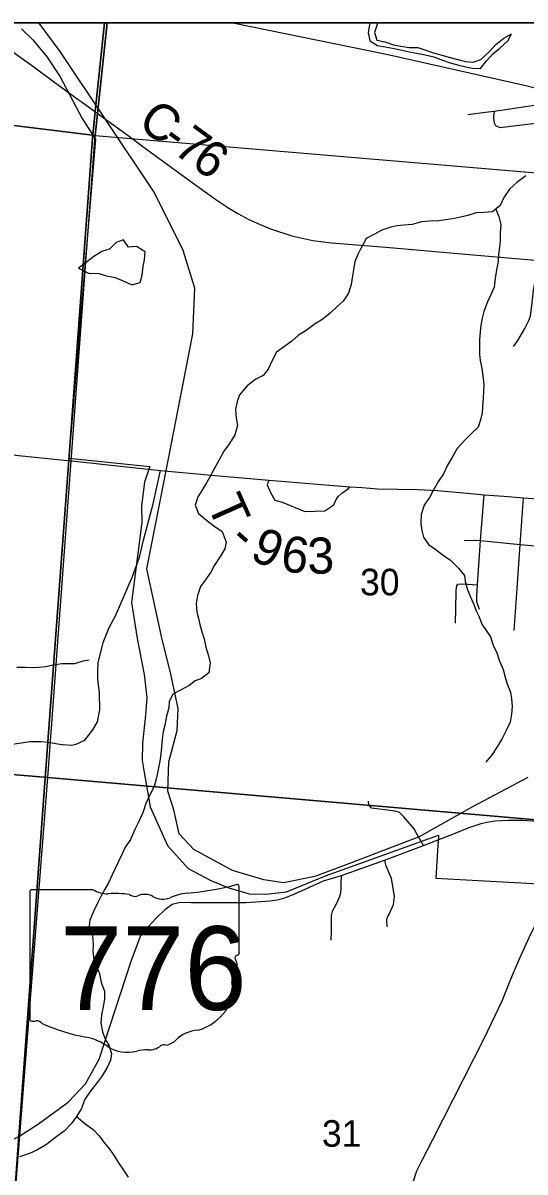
# Model space of a CAD drawing. Extents: x 0 to 42, y 0 to 22.
# Drawn here: x 2.271 to 2.666, y 19.995 to 20.9 of the extents above; entities that cross this region are included whole.
import ezdxf

# ---------------------------------------------------------------- set-up
doc = ezdxf.new("R2010")
doc.units = 0
for name, color, linetype in [('GM_X_City_Street', 7, 'Continuous'), ('GM_X_County_Road', 7, 'Continuous'), ('GM_X_County_Road_Text', 7, 'Continuous'), ('GM_X_Minor_Lake', 7, 'Continuous'), ('GM_X_Minor_River', 7, 'Continuous'), ('GM_X_Rail_Line', 7, 'Continuous'), ('GM_X_Section', 7, 'Continuous'), ('GM_X_Section_Text', 7, 'Continuous'), ('GM_X_State_Location', 7, 'Continuous'), ('GM_X_State_Route', 7, 'Continuous'), ('GM_X_State_Shield', 7, 'Continuous'), ('GM_X_Township_Road', 7, 'Continuous'), ('GM_X_Township_Road_Text', 7, 'Continuous'), ('GM_X_Unincorporated', 7, 'Continuous'), ('SH_Cut_Line', 7, 'Continuous'), ('SH_Data', 7, 'Continuous')]:
    doc.layers.add(name, color=color, linetype=linetype)

msp = doc.modelspace()

# ---------------------------------------------------------------- linework, layer by layer
at = {"layer": 'GM_X_City_Street'}
for points in [[(2.69353, 20.84243), (2.69352, 20.83798), (2.68544, 20.8369), (2.6506, 20.83163), (2.64714, 20.83111), (2.64496, 20.83077), (2.64156, 20.83021), (2.64126, 20.82626), (2.64118, 20.82527), (2.6417, 20.82134), (2.64286, 20.81923), (2.64611, 20.81767), (2.69164, 20.82305), (2.69375, 20.82356), (2.69547, 20.82473), (2.69654, 20.82659), (2.69573, 20.83522), (2.69441, 20.83772), (2.70111, 20.83974)], [(2.65681, 20.64514), (2.66032, 20.64991), (2.66593, 20.65926), (2.66875, 20.66505), (2.67022, 20.66916), (2.67142, 20.67721), (2.67273, 20.68948), (2.67716, 20.71289)], [(2.63006, 20.43787), (2.62809, 20.44409), (2.62809, 20.44853), (2.62858, 20.45731), (2.63105, 20.49224), (2.63388, 20.52836)], [(2.65749, 20.42134), (2.65981, 20.4545), (2.66213, 20.48923), (2.66487, 20.52594)], [(2.61812, 20.49239), (2.62596, 20.49264), (2.63105, 20.49224), (2.66213, 20.48923), (2.69114, 20.48647), (2.717, 20.4843), (2.74527, 20.48168), (2.79589, 20.47848), (2.83147, 20.47611), (2.86545, 20.47423)], [(2.61299, 20.4579), (2.61664, 20.4581), (2.62858, 20.45731)]]:
    msp.add_lwpolyline(points, dxfattribs=at)
at = {"layer": 'GM_X_County_Road'}
for points in [[(2.20921, 20.9), (2.22543, 20.89514), (2.24125, 20.88957), (2.25074, 20.88463), (2.26084, 20.87868), (2.27914, 20.86534)], [(2.27914, 20.86534), (2.2947, 20.85399), (2.31418, 20.83976)], [(2.31418, 20.83976), (2.31651, 20.83806), (2.32607, 20.83118)], [(2.32607, 20.83118), (2.32767, 20.83004), (2.33072, 20.82784), (2.33385, 20.82556)], [(2.33385, 20.82556), (2.35337, 20.81127), (2.36502, 20.80273), (2.38441, 20.78861), (2.4075, 20.77182), (2.42262, 20.76089), (2.43199, 20.75452), (2.43974, 20.74989), (2.44843, 20.74522), (2.45267, 20.74327)], [(2.45267, 20.74327), (2.45733, 20.74113), (2.46555, 20.73782), (2.48227, 20.73239), (2.4989, 20.72874), (2.51365, 20.72692), (2.55638, 20.72336), (2.62526, 20.71749), (2.67716, 20.71289), (2.68633, 20.71141), (2.69502, 20.70929), (2.70165, 20.7068), (2.70923, 20.70317), (2.7129, 20.70096)], [(2.30136, 20.33173), (2.30186, 20.33165), (2.30888, 20.33112), (2.31256, 20.33182), (2.31922, 20.33516), (2.32554, 20.34305), (2.32923, 20.34937), (2.33115, 20.35884), (2.33098, 20.37253), (2.32957, 20.38288), (2.32955, 20.38905), (2.32982, 20.39588), (2.33383, 20.41193), (2.33864, 20.42371), (2.34346, 20.43307), (2.357, 20.46397), (2.36231, 20.47917), (2.36526, 20.49142), (2.37308, 20.52124), (2.37897, 20.5476), (2.41898, 20.54388), (2.46428, 20.53976), (2.52797, 20.53458), (2.53771, 20.53402), (2.54991, 20.53312), (2.58119, 20.53245), (2.59708, 20.53164), (2.61455, 20.53024), (2.6205, 20.52966)], [(2.6205, 20.52966), (2.63388, 20.52836), (2.64928, 20.52713), (2.66487, 20.52594), (2.69112, 20.52409), (2.72008, 20.52113), (2.7486, 20.51783)], [(2.1, 20.25142), (2.10013, 20.25149), (2.12052, 20.26503), (2.17239, 20.30097), (2.18227, 20.30636), (2.19777, 20.31512), (2.20181, 20.31715), (2.20563, 20.31872), (2.2227, 20.32344), (2.23713, 20.32709), (2.26415, 20.33218), (2.27607, 20.33393), (2.28485, 20.3341), (2.29039, 20.33348), (2.30136, 20.33173)], [(2.59331, 20.02036), (2.63377, 20.09998), (2.64803, 20.12982), (2.65529, 20.14818), (2.66163, 20.1627), (2.67087, 20.18304), (2.67774, 20.19584), (2.68936, 20.21697), (2.69147, 20.22086)], [(2.49833, 19.78497), (2.50062, 19.79005), (2.50971, 19.80748), (2.53135, 19.84827), (2.54322, 19.8796), (2.58053, 19.99503), (2.5808, 19.99588), (2.58508, 20.00417), (2.59331, 20.02036)]]:
    msp.add_lwpolyline(points, dxfattribs=at)
at = {"layer": 'GM_X_Minor_Lake'}
for points in [[(2.36289, 20.69554), (2.36441, 20.70142), (2.36518, 20.70843), (2.36632, 20.71354), (2.3669, 20.7198), (2.36009, 20.72398), (2.35366, 20.72341), (2.34969, 20.72911), (2.34402, 20.72703), (2.33871, 20.72192), (2.33674, 20.72128)], [(2.33674, 20.72128), (2.33285, 20.72003), (2.32641, 20.71605), (2.32054, 20.71151), (2.31448, 20.70678), (2.32223, 20.70298), (2.33036, 20.70259), (2.33641, 20.70088), (2.34322, 20.69954), (2.35003, 20.6965), (2.35646, 20.69365), (2.36289, 20.69554)]]:
    msp.add_lwpolyline(points, dxfattribs=at)
at = {"layer": 'GM_X_Minor_River'}
for points in [[(2.54388, 20.9), (2.54325, 20.89719), (2.54248, 20.89226), (2.5438, 20.88581), (2.54985, 20.88239), (2.5559, 20.88125), (2.56157, 20.88011), (2.568, 20.87877), (2.575, 20.87725), (2.58086, 20.87629), (2.58748, 20.87496), (2.5941, 20.87324), (2.60091, 20.87058), (2.60715, 20.86868), (2.61377, 20.86678), (2.61944, 20.86544), (2.62455, 20.8643), (2.63098, 20.8641), (2.63553, 20.87016), (2.64102, 20.87584), (2.64594, 20.88001), (2.65238, 20.88587), (2.65542, 20.89156)], [(2.54982, 20.9), (2.54968, 20.89869), (2.5474, 20.89263), (2.54929, 20.88637), (2.55572, 20.88504), (2.56233, 20.88276), (2.5682, 20.8818), (2.57482, 20.88066), (2.58163, 20.88065), (2.58787, 20.87856), (2.59354, 20.87647), (2.59959, 20.87494), (2.60602, 20.87304), (2.61302, 20.87133), (2.61907, 20.86961), (2.62512, 20.86904), (2.63118, 20.8713), (2.6378, 20.87717), (2.6433, 20.88342), (2.64917, 20.88796), (2.65542, 20.89156)], [(2.66657, 20.77961), (2.65954, 20.77435), (2.65382, 20.76908), (2.64924, 20.76248), (2.64636, 20.75624), (2.64046, 20.75116), (2.63364, 20.75064), (2.62759, 20.75049), (2.62095, 20.74845), (2.61527, 20.74716), (2.61053, 20.74586), (2.60352, 20.74496), (2.59784, 20.74424), (2.59065, 20.74391), (2.5844, 20.74338), (2.57701, 20.74116), (2.57076, 20.74063), (2.56508, 20.7401), (2.56035, 20.73918), (2.55333, 20.73676), (2.54687, 20.73339), (2.5408, 20.73021), (2.53677, 20.72247), (2.53428, 20.71755), (2.53197, 20.71207), (2.53079, 20.70544), (2.53, 20.70071), (2.52901, 20.69408), (2.52707, 20.68727), (2.52286, 20.68085), (2.51811, 20.67671), (2.51258, 20.67144), (2.50669, 20.66674), (2.50061, 20.66299), (2.49281, 20.65716), (2.48768, 20.65416), (2.48235, 20.64946), (2.4776, 20.64589), (2.47018, 20.64063), (2.46692, 20.63421), (2.46366, 20.6274), (2.45965, 20.62231), (2.45395, 20.61932), (2.44711, 20.61405), (2.44119, 20.60708), (2.43927, 20.60178), (2.4379, 20.59553), (2.43842, 20.58908), (2.43952, 20.58282), (2.43739, 20.57563), (2.43336, 20.56864), (2.42878, 20.56261), (2.42476, 20.55543), (2.42112, 20.54882), (2.41824, 20.54315), (2.41518, 20.53786), (2.41193, 20.53238), (2.40829, 20.52672)], [(2.64298, 20.75334), (2.64535, 20.74753), (2.64682, 20.74126), (2.6464, 20.73482), (2.64636, 20.72856), (2.64594, 20.72345), (2.64515, 20.71758), (2.64492, 20.71208), (2.64355, 20.70564), (2.64237, 20.69902), (2.64157, 20.69182), (2.63887, 20.6852), (2.63638, 20.68029), (2.63349, 20.67273), (2.63232, 20.66743), (2.63115, 20.66194), (2.63054, 20.65644), (2.63012, 20.65076), (2.63009, 20.64526), (2.63023, 20.63881), (2.63077, 20.63407), (2.63186, 20.62819), (2.63313, 20.62003), (2.63347, 20.61509), (2.63325, 20.61017), (2.63302, 20.60448), (2.6326, 20.59766), (2.63219, 20.59292), (2.63083, 20.58743), (2.62908, 20.58157), (2.62432, 20.57705), (2.61804, 20.57083), (2.61251, 20.5648), (2.60925, 20.55876), (2.60485, 20.55158), (2.60178, 20.54497), (2.59796, 20.53912), (2.59374, 20.53175), (2.59068, 20.52627), (2.58666, 20.52004), (2.58415, 20.51286), (2.58392, 20.50565), (2.58463, 20.50015), (2.58592, 20.49502), (2.59005, 20.48912), (2.59494, 20.48567), (2.60153, 20.48089), (2.60737, 20.47687), (2.61357, 20.47057), (2.61826, 20.46485), (2.61898, 20.46011), (2.62064, 20.45346), (2.62288, 20.44852), (2.62567, 20.44186), (2.62753, 20.43692), (2.62977, 20.43217), (2.632, 20.42646), (2.63537, 20.42132), (2.63874, 20.41656), (2.64097, 20.40991), (2.64376, 20.40382), (2.64562, 20.39812), (2.64878, 20.39071), (2.65063, 20.38349), (2.65211, 20.37874), (2.65453, 20.37285), (2.65544, 20.36753), (2.65577, 20.36146), (2.65535, 20.3554), (2.65418, 20.34934), (2.6513, 20.34329), (2.64784, 20.33573), (2.64344, 20.32893), (2.64019, 20.32364), (2.63523, 20.31761)], [(2.40829, 20.52672), (2.40617, 20.5201), (2.40896, 20.51363), (2.41517, 20.50847), (2.421, 20.50389), (2.42759, 20.49929), (2.43075, 20.49093), (2.42958, 20.48582), (2.42652, 20.48053), (2.42155, 20.47298), (2.41848, 20.46731), (2.41485, 20.46222), (2.41046, 20.45618), (2.40795, 20.44899), (2.40715, 20.44274), (2.40748, 20.43591), (2.40878, 20.43097), (2.40988, 20.42623), (2.41173, 20.41958), (2.41321, 20.41483), (2.41468, 20.40818), (2.41671, 20.40153), (2.418, 20.39603), (2.417, 20.38807), (2.4111, 20.38356), (2.40636, 20.38169), (2.40141, 20.37812), (2.39458, 20.37438), (2.38869, 20.37138), (2.38581, 20.36514), (2.3854, 20.36041), (2.38365, 20.35397), (2.38247, 20.34696), (2.38092, 20.34186), (2.38012, 20.3356), (2.3797, 20.32954), (2.37929, 20.32404), (2.37849, 20.31855), (2.37712, 20.31192), (2.37576, 20.30549), (2.37401, 20.29867), (2.37055, 20.29187), (2.36748, 20.28525), (2.36536, 20.27863), (2.3619, 20.27088), (2.35864, 20.26464), (2.35518, 20.2567), (2.35078, 20.25029), (2.34867, 20.24537), (2.34579, 20.23951), (2.34329, 20.23384), (2.3408, 20.22893), (2.33792, 20.22269), (2.33505, 20.21778), (2.33217, 20.2123), (2.32968, 20.20719), (2.32622, 20.20001), (2.32334, 20.19321), (2.32274, 20.18847), (2.32479, 20.18353), (2.3257, 20.17878), (2.32585, 20.17366), (2.32563, 20.16892), (2.32653, 20.16209), (2.3282, 20.15715), (2.331, 20.15125), (2.33209, 20.14404), (2.33488, 20.13738), (2.33484, 20.13132), (2.33385, 20.12487), (2.33248, 20.11863), (2.33206, 20.11199), (2.33315, 20.10516), (2.33556, 20.09908), (2.33856, 20.09413), (2.34041, 20.08786), (2.33962, 20.08293), (2.33693, 20.07707), (2.33291, 20.07065), (2.32909, 20.06537), (2.32356, 20.05839), (2.31916, 20.05159), (2.31665, 20.04478), (2.31283, 20.03855), (2.30862, 20.0327), (2.30329, 20.02724), (2.29625, 20.02216), (2.28921, 20.01652), (2.28219, 20.01239), (2.27573, 20.0094), (2.26796, 20.0068)], [(2.32284, 20.39798), (2.31773, 20.39726), (2.31128, 20.39521), (2.30617, 20.39506), (2.30126, 20.39528), (2.29444, 20.39419), (2.28875, 20.39271), (2.28307, 20.39237), (2.27777, 20.39202), (2.27248, 20.39225), (2.26586, 20.39229)], [(2.31283, 20.03855), (2.31941, 20.03301), (2.32581, 20.02841), (2.3307, 20.02345), (2.33407, 20.0185), (2.33914, 20.01259), (2.34307, 20.00687), (2.34588, 20.00211), (2.34925, 19.99697), (2.35356, 19.99088)]]:
    msp.add_lwpolyline(points, dxfattribs=at)
at = {"layer": 'GM_X_Rail_Line'}
for points in [[(2.66817, 20.30566), (2.62461, 20.28264), (2.58268, 20.2588), (2.52432, 20.23661), (2.50048, 20.22757), (2.47582, 20.22264), (2.4602, 20.2251), (2.43554, 20.2325), (2.40513, 20.24894), (2.39362, 20.26127), (2.38951, 20.28018), (2.38458, 20.29497), (2.3854, 20.31799), (2.39198, 20.34265), (2.3928, 20.35991), (2.38704, 20.38704), (2.37965, 20.41663), (2.36814, 20.47006), (2.3854, 20.55802), (2.40431, 20.65502), (2.40595, 20.69119), (2.39691, 20.72078), (2.37389, 20.76681), (2.29987, 20.87747), (2.28347, 20.89998), (2.28344, 20.9)], [(2.43589, 20.9), (2.55679, 20.87545), (2.66669, 20.85076), (2.98339, 20.77295), (3.02658, 20.75958)]]:
    msp.add_lwpolyline(points, dxfattribs=at)
at = {"layer": 'GM_X_Section'}
for points in [[(2.32754, 20.81125), (2.88887, 20.76389), (2.8507, 20.2571), (2.29013, 20.3056)], [(2.29013, 20.3056), (2.8507, 20.2571), (2.81539, 19.7575), (2.79152, 19.75944), (2.25084, 19.80525)]]:
    msp.add_lwpolyline(points, close=True, dxfattribs=at)
at = {"layer": 'GM_X_State_Route'}
for points in [[(3.54361, 20.9), (3.36487, 20.9), (3.35986, 20.89744), (3.3487, 20.89096), (3.33142, 20.878), (3.30883, 20.85769), (3.28419, 20.8256), (3.29069, 20.9), (2.26236, 20.9)], [(2.26937, 20.89534), (2.2785, 20.88681), (2.28973, 20.87316), (2.30001, 20.85761), (2.31735, 20.82479), (2.32777, 20.80836), (2.30662, 20.55707), (2.37058, 20.55053), (2.36629, 20.53832), (2.36404, 20.51951), (2.36426, 20.50641), (2.35621, 20.44353), (2.36063, 20.41523), (2.366, 20.38676), (2.36812, 20.36853), (2.36719, 20.35466), (2.36477, 20.33262), (2.36441, 20.31895), (2.36575, 20.31122), (2.37074, 20.28249), (2.38447, 20.25194), (2.40083, 20.23393), (2.41868, 20.22443), (2.43277, 20.21866), (2.44871, 20.21388), (2.46211, 20.21381), (2.47805, 20.21566), (2.50878, 20.22813), (2.59786, 20.26026), (2.59774, 20.25817), (2.59739, 20.25239), (2.59585, 20.22636), (2.69136, 20.22112)], [(2.60027, 20.25763), (2.60498, 20.25952), (2.62279, 20.26642), (2.63133, 20.26938), (2.63602, 20.27047), (2.64243, 20.27155), (2.65289, 20.27215), (2.66409, 20.2721), (2.67611, 20.27131), (2.68429, 20.27066)], [(2.52148, 20.22856), (2.55544, 20.2406), (2.58613, 20.25197), (2.60027, 20.25763)], [(2.4934, 20.21804), (2.50717, 20.22421), (2.52148, 20.22856)], [(2.28279, 20.03291), (2.30617, 20.04993), (2.3199, 20.06441), (2.33061, 20.08383), (2.35582, 20.16082), (2.36324, 20.18054), (2.36695, 20.18541), (2.37554, 20.19475), (2.38309, 20.20218), (2.38808, 20.20589), (2.39449, 20.2073), (2.40307, 20.20717), (2.44634, 20.20705), (2.4653, 20.20845), (2.47093, 20.20935), (2.47605, 20.2105), (2.47772, 20.21121), (2.48514, 20.21434), (2.4934, 20.21804)], [(2.1, 19.96572), (2.12821, 19.95336), (2.13381, 19.95139), (2.1394, 19.95064), (2.14434, 19.95048), (2.14782, 19.95153), (2.15117, 19.95246), (2.15677, 19.95517), (2.16558, 19.96242), (2.18591, 19.98617), (2.19546, 19.99573), (2.21159, 20.00593), (2.22443, 20.0112), (2.24438, 20.01531), (2.25604, 20.01713), (2.26748, 20.02277), (2.28199, 20.03232), (2.28279, 20.03291)]]:
    msp.add_lwpolyline(points, dxfattribs=at)
at = {"layer": 'GM_X_State_Shield'}
for p, q in [((2.27603, 20.21552), (2.27603, 20.11546)), ((2.32591, 20.21724), (2.27765, 20.21724)), ((2.44082, 20.16738), (2.44082, 20.21972)), ((2.4408, 20.16739), (2.44082, 20.16738))]:
    msp.add_line(p, q, dxfattribs=at)
for centre, major_axis, start_param, end_param in [((2.38212, 20.35366), (0.17476, 0), 4.814394, 5.042369), ((2.43899, 20.21994), (0.00183, 0), 6.141152, 7.989035), ((2.27792, 20.21574), (0.00191, 0), 1.712693, 3.28349), ((2.3374, 20.22886), (0.01852, 0), 4.042523, 4.731795), ((2.34354, 20.16107), (0.06648, 0), 1.404758, 1.657858), ((2.35864, 20.21625), (0.00534, 0), 3.836095, 5.185415), ((2.36648, 20.20469), (0.01111, 0), 0.950623, 2.079405), ((2.40441, 20.18668), (0.03516, 0), 1.699011, 2.107814), ((2.38081, 20.22055), (0.01336, 0), 4.081561, 5.145723), ((2.43886, 20.16718), (0.00196, 0), 5.05454, 6.418171), ((2.4404, 20.16354), (0.00284, 0), 1.883978, 3.671073), ((2.42233, 20.15692), (0.01704, 0), 5.934695, 6.695948), ((2.44739, 20.14548), (0.0124, 0), 2.387724, 3.262537), ((2.39191, 20.13882), (0.04371, 0), 5.101752, 6.440018), ((2.27793, 20.11524), (0.00193, 0), 3.00124, 4.508301), ((2.27823, 20.12548), (0.0147, 0), 4.665946, 4.897461), ((2.28123, 20.10969), (0.0053, 0), 0.519207, 1.627899), ((2.34815, 20.19959), (0.1262, 0), 4.195997, 4.488961), ((2.41034, 20.08737), (0.02394, 0), 1.647645, 2.488434), ((2.31052, 20.07051), (0.03949, 0), 0.823519, 1.323587), ((2.38161, 20.09201), (0.00376, 0), 1.147584, 2.315152), ((2.38001, 20.10576), (0.01412, 0), 4.937069, 5.64225), ((2.35323, 20.10919), (0.02506, 0), 4.026481, 4.996735), ((2.3677, 20.0746), (0.02059, 0), 1.495662, 1.94098), ((2.36953, 20.1017), (0.01335, 0), 4.691044, 5.507374)]:
    msp.add_ellipse(centre, major_axis=major_axis, ratio=0.8, start_param=start_param, end_param=end_param, dxfattribs=at)
at = {"layer": 'GM_X_Township_Road'}
msp.add_line((2.61111, 20.42716), (2.61166, 20.45111), dxfattribs=at)
msp.add_lwpolyline([(2.33491, 20.9), (2.1, 20.9), (2.1, 19.81647), (2.25126, 19.80438), (2.26737, 20.02303), (2.29028, 20.33374), (2.30663, 20.5555), (2.32532, 20.80909), (2.32756, 20.8303)], close=True, dxfattribs=at)
for points in [[(5.44663, 20.9), (2.33491, 20.9), (2.32756, 20.8303), (2.32532, 20.80909), (2.30663, 20.5555), (2.29028, 20.33374), (2.26737, 20.02303)], [(2.64156, 20.83021), (2.63699, 20.82967), (2.62104, 20.82775)], [(2.10644, 20.53517), (2.1238, 20.54129), (2.148, 20.55131), (2.16338, 20.55878), (2.17452, 20.56268), (2.18544, 20.56547), (2.19547, 20.56669), (2.20988, 20.56648), (2.26724, 20.55934), (2.30319, 20.55561)], [(2.30319, 20.55561), (2.30673, 20.55524), (2.33782, 20.55194), (2.37897, 20.5476)], [(2.46428, 20.53976), (2.46289, 20.53615), (2.46556, 20.53009), (2.46906, 20.52407), (2.47483, 20.52249), (2.49251, 20.51515), (2.50823, 20.51561), (2.51544, 20.52032), (2.51727, 20.52451), (2.51872, 20.52708), (2.52166, 20.52949), (2.52699, 20.53319), (2.52797, 20.53458)], [(2.61166, 20.45111), (2.61171, 20.45316), (2.61235, 20.45672), (2.61299, 20.4579)], [(2.58613, 20.25197), (2.58095, 20.26068), (2.57857, 20.26517), (2.57065, 20.27454), (2.56722, 20.27811), (2.56379, 20.27916), (2.55336, 20.28048), (2.54517, 20.28141), (2.54312, 20.28403), (2.54268, 20.28693)], [(2.55544, 20.2406), (2.55615, 20.23678), (2.5606, 20.22635), (2.56281, 20.21185), (2.56207, 20.20522), (2.55888, 20.19834), (2.5578, 20.19624), (2.55697, 20.19361), (2.55718, 20.18794)], [(2.52148, 20.22856), (2.5209, 20.2244), (2.52101, 20.2184), (2.52067, 20.21447), (2.51963, 20.21112), (2.51755, 20.20638), (2.5142, 20.20003), (2.51327, 20.19691), (2.5132, 20.18466), (2.51316, 20.1775)]]:
    msp.add_lwpolyline(points, dxfattribs=at)
at = {"layer": 'GM_X_Unincorporated'}
for points in [[(2.33688, 20.9), (2.1, 20.9), (2.1, 20.83342), (2.20123, 20.82686), (2.32754, 20.81125)], [(2.90183, 20.9), (2.33688, 20.9), (2.32754, 20.81125), (2.88887, 20.76389)], [(2.1, 20.83342), (2.1, 20.3216), (2.29013, 20.3056), (2.32754, 20.81125), (2.20123, 20.82686)], [(2.1, 20.3216), (2.1, 19.81609), (2.25084, 19.80525), (2.29013, 20.3056)]]:
    msp.add_lwpolyline(points, close=True, dxfattribs=at)
at = {"layer": 'SH_Cut_Line'}
msp.add_lwpolyline([(8.604, 20.9), (2.1, 20.9), (2.1, 14.1)], dxfattribs=at)
at = {"layer": 'SH_Data'}
msp.add_line((2.1, 20.9), (8.9, 20.9), dxfattribs=at)

# ---------------------------------------------------------------- texts
at = {"layer": 'GM_X_County_Road_Text'}
for s, rotation, p in [('C', 323.72935, (2.35981, 20.81889)), ('7', 323.81357, (2.38785, 20.79833)), ('-', 323.80466, (2.37852, 20.80517)), ('6', 323.97021, (2.40193, 20.78803))]:
    msp.add_text(s, height=0.02841, rotation=rotation, dxfattribs=at).set_placement(p)
at = {"layer": 'GM_X_Section_Text'}
for s, p in [('30', (2.53606, 20.44913)), ('31', (2.50606, 20.01475))]:
    msp.add_text(s, height=0.020928, rotation=0.00001, dxfattribs=at).set_placement(p)
at = {"layer": 'GM_X_State_Location'}
for s in ['s', 'r']:
    msp.add_text(s, height=0.0000947, dxfattribs=at).set_placement((2.35657, 20.15884))
msp.add_text('776', height=0.0000947, rotation=0.00001, dxfattribs=at).set_placement((2.32314, 20.15195))
at = {"layer": 'GM_X_State_Shield'}
msp.add_text('776', height=0.065918, dxfattribs=at).set_placement((2.29974, 20.12252))
at = {"layer": 'GM_X_Township_Road_Text'}
for s, rotation, p in [('T', 293.99209, (2.41513, 20.52088)), ('9', 336.13189, (2.44826, 20.47798)), ('-', 318.39408, (2.43151, 20.4909)), ('6', 352.47992, (2.47275, 20.46852)), ('3', 1.32835, (2.49487, 20.46597))]:
    msp.add_text(s, height=0.02841, rotation=rotation, dxfattribs=at).set_placement(p)

doc.saveas('drawing.dxf')
